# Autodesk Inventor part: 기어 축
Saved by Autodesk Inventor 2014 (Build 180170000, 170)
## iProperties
Created: 2026-04
Part Number: 기어 축
Material: 강철, 합금
Document SubType Name: Modeling
Designer: dg
Density: 7.85 g/cm^3
Appearance: 반연마
Author: jhkim
Creation Date: 2026-03-27
Sending System: Autodesk Inventor 2026
Preprocessor: ST-DEVELOPER v20.1
Author: dg
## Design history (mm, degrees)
node "기어 축1"
node "솔리드1"
node "기준1"
